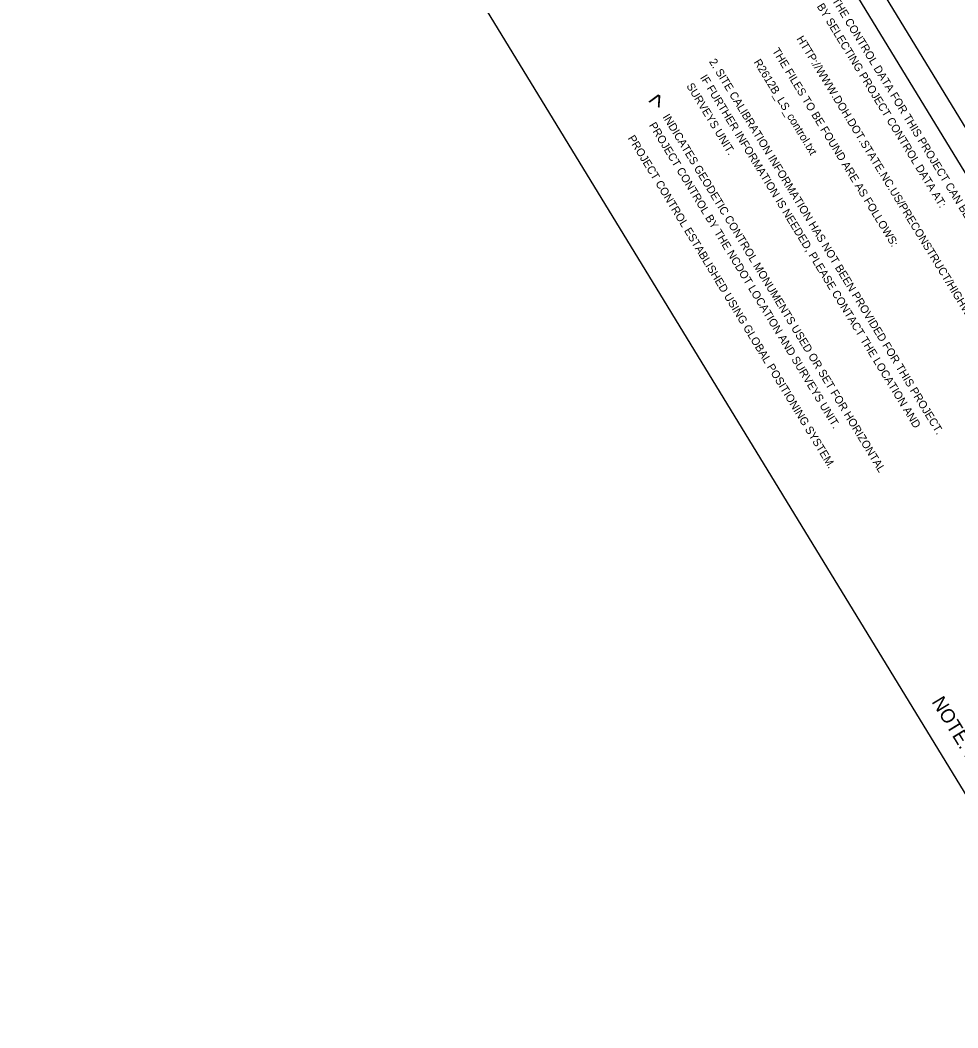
# Model space of a CAD drawing. Extents: x 1753086 to 1770987, y 792577 to 812636.
# Drawn here: x 1753162 to 1760195, y 792577 to 800134 of the extents above; entities that cross this region are included whole.
import ezdxf

# ---------------------------------------------------------------- set-up
doc = ezdxf.new("R2010")
doc.units = 0
for name, color, linetype in [('CTL Sheet Border CELL', 7, 'Continuous'), ('Old_Level_2', 7, 'Continuous'), ('Old_Level_57', 7, 'Continuous'), ('Sheet Data Field CELL', 7, 'Continuous')]:
    doc.layers.add(name, color=color, linetype=linetype)

msp = doc.modelspace()

# ---------------------------------------------------------------- linework, layer by layer
at = {"layer": 'CTL Sheet Border CELL'}
for points in [[(1770671.7, 798289.4), (1762511, 811645.8), (1753161.6, 805933.4), (1761322.3, 792577)], [(1759320.2, 800854.1), (1761948.9, 796551.8), (1761798.1, 796459.7), (1759169.5, 800761.8)]]:
    msp.add_lwpolyline(points, close=True, dxfattribs=at)

# ---------------------------------------------------------------- texts
at = {"layer": 'Old_Level_2'}
for s, rotation, p in [('1. THE CONTROL DATA FOR THIS PROJECT CAN BE FOUND ELECTRONICALLY', 301.42495, (1759202.6, 800357.2)), ('   BY SELECTING PROJECT CONTROL DATA AT:', 301.42495, (1759100.2, 800294.7)), ('HTTP://WWW.DOH.DOT.STATE.NC.US/PRECONSTRUCT/HIGHWAY/LOCATION/PROJECT/', 301.42495, (1758982.7, 799993.9)), ('THE FILES TO BE FOUND ARE AS FOLLOWS:', 301.42495, (1758800.7, 799903.8)), ('2. SITE CALIBRATION INFORMATION HAS NOT BEEN PROVIDED FOR THIS PROJECT.', 301.42495, (1758327, 799822.6)), ('R2612B_LS_control.txt', 301.42495, (1758662, 799819.1)), ('   IF FURTHER INFORMATION IS NEEDED, PLEASE CONTACT THE LOCATION AND', 301.42495, (1758224.6, 799760)), ('   SURVEYS UNIT.', 301.42495, (1758122.2, 799697.5)), ('INDICATES GEODETIC CONTROL MONUMENTS USED OR SET FOR HORIZONTAL', 301.3197, (1757978.6, 799408)), ('PROJECT CONTROL BY THE NCDOT LOCATION AND SURVEYS UNIT.', 301.3197, (1757876.1, 799345.6)), ('PROJECT CONTROL ESTABLISHED USING GLOBAL POSITIONING SYSTEM.', 301.3197, (1757717.6, 799248.5))]:
    msp.add_text(s, height=60, rotation=rotation, dxfattribs=at).set_placement(p)
at = {"layer": 'Old_Level_57'}
msp.add_text('>', height=130.4, rotation=61.33407, dxfattribs=at).set_placement((1757965.4, 799460.9))
at = {"layer": 'Sheet Data Field CELL'}
msp.add_text('NOTE: DRAWING NOT TO SCALE', height=104.348, rotation=301.3197, dxfattribs=at).set_placement((1759995.9, 795022.1))

doc.saveas('drawing.dxf')
